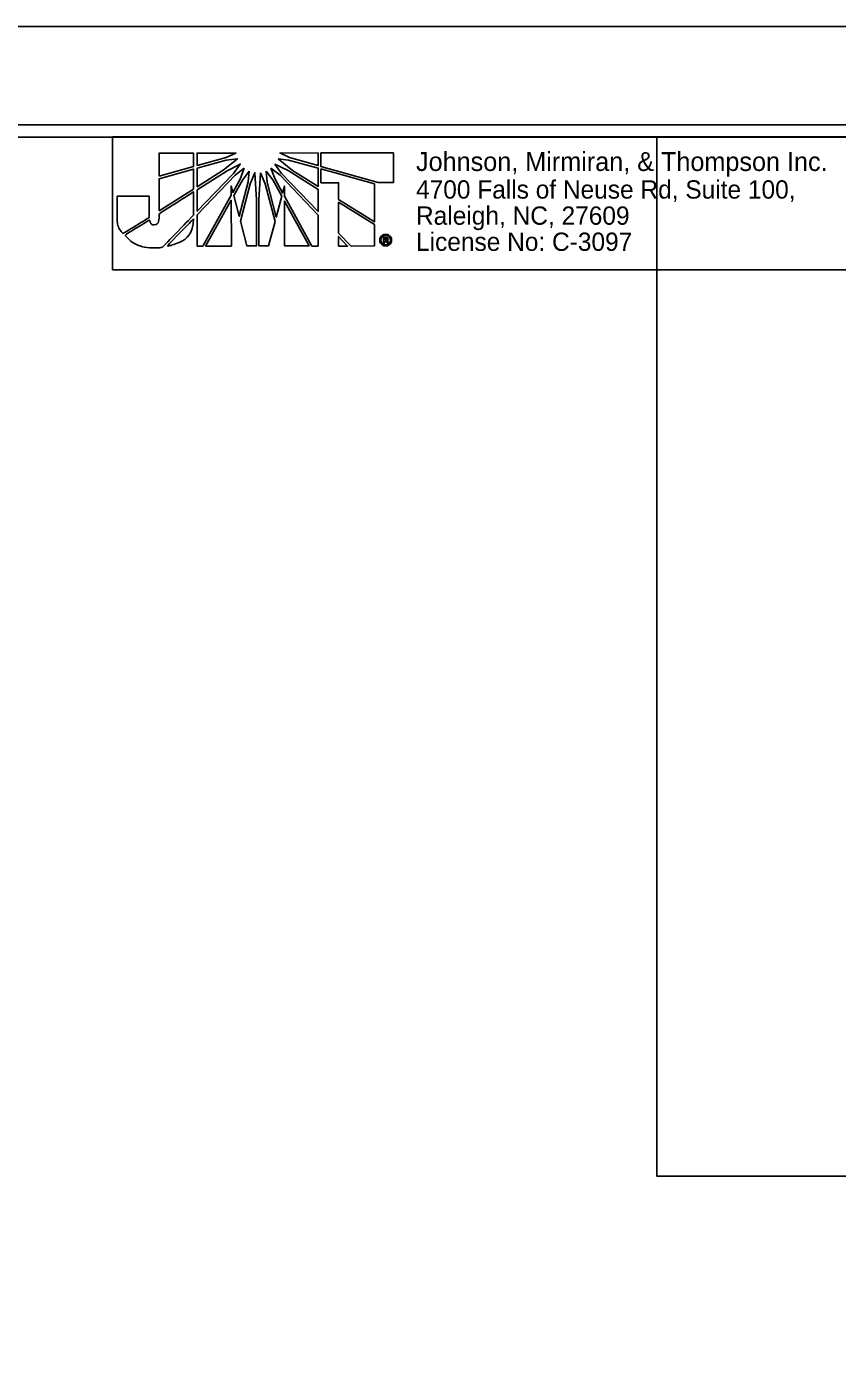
# Model space of a CAD drawing. Extents: x 1640342 to 1730599, y 538663 to 843747.
# Drawn here: x 1730100.5 to 1730133.5, y 539076.9 to 539130.9 of the extents above; entities that cross this region are included whole.
import ezdxf

# ---------------------------------------------------------------- set-up
doc = ezdxf.new("R2010")
doc.units = 0
for name, color, linetype in [('Prop Dimension Text', 7, 'Continuous'), ('Sheet Clip Boundary CELL', 7, 'Continuous'), ('Sheet Layout Plan Border', 7, 'Continuous'), ('Sheet Plan CELL', 7, 'Continuous'), ('Sheet Plan Layout CELL', 7, 'Continuous'), ('Sheet Plot Border Inside CELL', 7, 'Continuous'), ('Sheet Plot Border Outside CELL', 7, 'Continuous')]:
    doc.layers.add(name, color=color, linetype=linetype)

msp = doc.modelspace()

# ---------------------------------------------------------------- linework, layer by layer
at = {"layer": 'Prop Dimension Text'}
for p, q in [((1730107.302, 539125.758), (1730105.899, 539125.756)), ((1730105.899, 539125.756), (1730105.9, 539124.826)), ((1730107.302, 539125.216), (1730107.302, 539125.758)), ((1730109.027, 539125.766), (1730107.448, 539125.765)), ((1730107.448, 539125.765), (1730107.448, 539125.262)), ((1730108.624, 539125.588), (1730109.027, 539125.766)), ((1730112.37, 539125.763), (1730110.814, 539125.768)), ((1730110.814, 539125.768), (1730111.208, 539125.583)), ((1730112.37, 539125.258), (1730112.37, 539125.763)), ((1730115.428, 539125.772), (1730112.479, 539125.77)), ((1730112.479, 539125.77), (1730112.479, 539125.228)), ((1730115.43, 539124.564), (1730115.428, 539125.772)), ((1730105.9, 539124.826), (1730107.302, 539125.216)), ((1730107.448, 539125.262), (1730108.624, 539125.588)), ((1730108.624, 539125.479), (1730107.448, 539125.154)), ((1730107.448, 539125.154), (1730107.449, 539124.394)), ((1730108.502, 539125.062), (1730109.082, 539125.535)), ((1730109.082, 539125.535), (1730108.624, 539125.479)), ((1730109.198, 539125.317), (1730108.664, 539125.046)), ((1730108.928, 539124.937), (1730109.198, 539125.317)), ((1730109.361, 539125.148), (1730108.988, 539124.861)), ((1730109.19, 539124.699), (1730109.361, 539125.148)), ((1730110.449, 539125.15), (1730110.621, 539124.701)), ((1730110.822, 539124.863), (1730110.449, 539125.15)), ((1730110.613, 539125.319), (1730110.884, 539124.932)), ((1730111.155, 539125.048), (1730110.613, 539125.319)), ((1730110.736, 539125.536), (1730111.324, 539125.055)), ((1730111.169, 539125.481), (1730110.736, 539125.536)), ((1730112.37, 539125.151), (1730111.169, 539125.481)), ((1730111.208, 539125.583), (1730112.37, 539125.258)), ((1730112.362, 539124.408), (1730112.37, 539125.151)), ((1730112.479, 539125.228), (1730112.479, 539125.212)), ((1730112.479, 539125.212), (1730114.802, 539124.563)), ((1730107.302, 539125.114), (1730105.9, 539124.719)), ((1730105.9, 539124.719), (1730105.901, 539123.411)), ((1730107.303, 539124.301), (1730107.302, 539125.114)), ((1730107.449, 539124.394), (1730108.502, 539125.062)), ((1730108.664, 539125.046), (1730107.449, 539124.271)), ((1730107.45, 539123.396), (1730108.928, 539124.937)), ((1730108.988, 539124.861), (1730107.45, 539123.248)), ((1730108.896, 539124.164), (1730109.19, 539124.699)), ((1730109.285, 539124.667), (1730108.936, 539124.032)), ((1730109.562, 539125.024), (1730109.285, 539124.667)), ((1730109.523, 539124.591), (1730109.562, 539125.024)), ((1730109.794, 539124.961), (1730109.602, 539124.512)), ((1730109.855, 539123.855), (1730109.794, 539124.961)), ((1730110.025, 539124.962), (1730109.954, 539123.855)), ((1730110.211, 539124.513), (1730110.025, 539124.962)), ((1730110.25, 539125.024), (1730110.296, 539124.575)), ((1730110.521, 539124.668), (1730110.25, 539125.024)), ((1730110.885, 539124.011), (1730110.521, 539124.668)), ((1730110.621, 539124.701), (1730110.922, 539124.143)), ((1730112.363, 539123.239), (1730110.822, 539124.863)), ((1730110.884, 539124.932), (1730112.363, 539123.385)), ((1730112.362, 539124.283), (1730111.155, 539125.048)), ((1730111.324, 539125.055), (1730112.362, 539124.408)), ((1730112.479, 539125.128), (1730112.479, 539125.119)), ((1730114.654, 539124.51), (1730112.479, 539125.128)), ((1730112.479, 539125.119), (1730112.48, 539124.554)), ((1730105.901, 539123.411), (1730107.303, 539124.301)), ((1730107.449, 539124.271), (1730107.45, 539123.396)), ((1730108.827, 539124.048), (1730108.826, 539124.419)), ((1730108.826, 539124.419), (1730108.896, 539124.164)), ((1730109.161, 539123.19), (1730109.523, 539124.591)), ((1730109.602, 539124.512), (1730109.208, 539122.995)), ((1730110.615, 539122.973), (1730110.211, 539124.513)), ((1730110.296, 539124.575), (1730110.661, 539123.159)), ((1730110.922, 539124.143), (1730110.994, 539124.421)), ((1730110.994, 539124.421), (1730110.994, 539124.011)), ((1730112.363, 539123.385), (1730112.362, 539124.283)), ((1730112.48, 539124.554), (1730113.2, 539124.555)), ((1730113.2, 539124.555), (1730113.201, 539123.881)), ((1730114.655, 539122.961), (1730114.654, 539124.51)), ((1730114.802, 539124.563), (1730115.43, 539124.564)), ((1730107.683, 539121.975), (1730108.827, 539124.048)), ((1730108.827, 539123.847), (1730107.792, 539121.975)), ((1730108.838, 539121.976), (1730108.827, 539123.847)), ((1730108.936, 539124.032), (1730109.161, 539123.19)), ((1730109.857, 539121.984), (1730109.855, 539123.855)), ((1730109.954, 539123.855), (1730109.956, 539121.984)), ((1730110.661, 539123.159), (1730110.885, 539124.011)), ((1730110.994, 539124.011), (1730112.116, 539121.979)), ((1730112.001, 539121.986), (1730110.994, 539123.809)), ((1730110.994, 539123.809), (1730110.996, 539121.985)), ((1730113.201, 539123.881), (1730114.655, 539122.961)), ((1730113.201, 539123.765), (1730113.202, 539122.51)), ((1730114.655, 539122.852), (1730113.201, 539123.765)), ((1730107.45, 539123.248), (1730107.451, 539121.975)), ((1730109.208, 539122.995), (1730109.472, 539121.984)), ((1730112.364, 539121.979), (1730112.363, 539123.239)), ((1730110.345, 539121.984), (1730110.615, 539122.973)), ((1730113.202, 539122.51), (1730113.705, 539121.981)), ((1730114.656, 539121.982), (1730114.655, 539122.852)), ((1730115.113, 539122.456), (1730115.113, 539122.411)), ((1730115.113, 539122.411), (1730115.113, 539122.456)), ((1730107.451, 539121.975), (1730107.683, 539121.975)), ((1730107.792, 539121.975), (1730108.838, 539121.976)), ((1730109.472, 539121.984), (1730109.857, 539121.984)), ((1730109.956, 539121.984), (1730110.345, 539121.984)), ((1730110.996, 539121.985), (1730112.001, 539121.986)), ((1730112.116, 539121.979), (1730112.364, 539121.979)), ((1730113.566, 539121.981), (1730113.202, 539122.374)), ((1730113.202, 539122.374), (1730113.202, 539121.98)), ((1730113.202, 539121.98), (1730113.566, 539121.981)), ((1730113.705, 539121.981), (1730114.656, 539121.982)), ((1730115.026, 539122.114), (1730115.025, 539122.329)), ((1730115.025, 539122.329), (1730115.113, 539122.329)), ((1730115.074, 539122.114), (1730115.026, 539122.114)), ((1730115.113, 539122.288), (1730115.074, 539122.288)), ((1730115.074, 539122.288), (1730115.074, 539122.237)), ((1730115.074, 539122.237), (1730115.113, 539122.237)), ((1730115.113, 539122.198), (1730115.074, 539122.198)), ((1730115.074, 539122.198), (1730115.074, 539122.114)), ((1730115.113, 539122.329), (1730115.113, 539122.288)), ((1730115.113, 539122.288), (1730115.113, 539122.329)), ((1730115.113, 539122.329), (1730115.127, 539122.329)), ((1730115.119, 539122.288), (1730115.113, 539122.288)), ((1730115.113, 539122.237), (1730115.113, 539122.198)), ((1730115.113, 539122.198), (1730115.113, 539122.237)), ((1730115.113, 539122.237), (1730115.115, 539122.237)), ((1730115.115, 539122.198), (1730115.113, 539122.198)), ((1730115.113, 539122.031), (1730115.114, 539121.984)), ((1730115.114, 539121.984), (1730115.113, 539122.031)), ((1730115.113, 539122.031), (1730115.115, 539122.031)), ((1730115.115, 539121.984), (1730115.114, 539121.984))]:
    msp.add_line(p, q, dxfattribs=at)
msp.add_lwpolyline([(1730104.001, 539121.01), (1730133.983, 539121.01), (1730133.983, 539126.42), (1730104.001, 539126.42)], close=True, dxfattribs=at)
for points in [[(1730105.9, 539124.826), (1730107.302, 539125.216), (1730107.302, 539125.758), (1730105.899, 539125.756), (1730105.9, 539124.826)], [(1730108.624, 539125.588), (1730109.027, 539125.766), (1730107.448, 539125.765), (1730107.448, 539125.262), (1730108.624, 539125.588)], [(1730111.208, 539125.583), (1730112.37, 539125.258), (1730112.37, 539125.763), (1730110.814, 539125.768), (1730111.208, 539125.583)], [(1730115.428, 539125.772), (1730112.479, 539125.77), (1730112.479, 539125.228), (1730112.479, 539125.212), (1730114.802, 539124.563), (1730115.43, 539124.564), (1730115.428, 539125.772)], [(1730107.448, 539125.154), (1730107.449, 539124.394), (1730108.502, 539125.062), (1730109.082, 539125.535), (1730108.624, 539125.479), (1730107.448, 539125.154)], [(1730107.449, 539124.271), (1730107.45, 539123.396), (1730108.928, 539124.937), (1730109.198, 539125.317), (1730108.664, 539125.046), (1730107.449, 539124.271)], [(1730109.361, 539125.148), (1730108.988, 539124.861), (1730107.45, 539123.248), (1730107.451, 539121.975), (1730107.683, 539121.975), (1730108.827, 539124.048), (1730108.826, 539124.419), (1730108.896, 539124.164), (1730109.19, 539124.699), (1730109.361, 539125.148)], [(1730110.449, 539125.15), (1730110.621, 539124.701), (1730110.922, 539124.143), (1730110.994, 539124.421), (1730110.994, 539124.011), (1730112.116, 539121.979), (1730112.364, 539121.979), (1730112.363, 539123.239), (1730110.822, 539124.863), (1730110.449, 539125.15)], [(1730110.613, 539125.319), (1730110.884, 539124.932), (1730112.363, 539123.385), (1730112.362, 539124.283), (1730111.155, 539125.048), (1730110.613, 539125.319)], [(1730110.736, 539125.536), (1730111.324, 539125.055), (1730112.362, 539124.408), (1730112.37, 539125.151), (1730111.169, 539125.481), (1730110.736, 539125.536)], [(1730105.901, 539123.411), (1730107.303, 539124.301), (1730107.302, 539125.114), (1730105.9, 539124.719), (1730105.901, 539123.411)], [(1730109.562, 539125.024), (1730109.285, 539124.667), (1730108.936, 539124.032), (1730109.161, 539123.19), (1730109.523, 539124.591), (1730109.562, 539125.024)], [(1730109.602, 539124.512), (1730109.208, 539122.995), (1730109.472, 539121.984), (1730109.857, 539121.984), (1730109.855, 539123.855), (1730109.794, 539124.961), (1730109.602, 539124.512)], [(1730110.025, 539124.962), (1730109.954, 539123.855), (1730109.956, 539121.984), (1730110.345, 539121.984), (1730110.615, 539122.973), (1730110.211, 539124.513), (1730110.025, 539124.962)], [(1730110.25, 539125.024), (1730110.296, 539124.575), (1730110.661, 539123.159), (1730110.885, 539124.011), (1730110.521, 539124.668), (1730110.25, 539125.024)], [(1730112.479, 539125.128), (1730112.479, 539125.119), (1730112.48, 539124.554), (1730113.2, 539124.555), (1730113.201, 539123.881), (1730114.655, 539122.961), (1730114.654, 539124.51), (1730112.479, 539125.128)], [(1730107.792, 539121.975), (1730108.838, 539121.976), (1730108.827, 539123.847), (1730107.792, 539121.975)], [(1730110.996, 539121.985), (1730112.001, 539121.986), (1730110.994, 539123.809), (1730110.996, 539121.985)], [(1730113.201, 539123.765), (1730113.202, 539122.51), (1730113.705, 539121.981), (1730114.656, 539121.982), (1730114.655, 539122.852), (1730113.201, 539123.765), (1730113.201, 539123.765)], [(1730113.202, 539121.98), (1730113.202, 539121.98), (1730113.566, 539121.981), (1730113.202, 539122.374), (1730113.202, 539121.98)], [(1730115.207, 539122.165), (1730115.207, 539122.154), (1730115.209, 539122.146), (1730115.209, 539122.138), (1730115.215, 539122.115), (1730115.17, 539122.115)]]:
    msp.add_lwpolyline(points, dxfattribs=at)
for points, degree in [([(1730105.7, 539122.844), (1730105.617, 539122.844), (1730105.545, 539122.89), (1730105.515, 539123.045), (1730105.515, 539123.045), (1730104.508, 539122.421), (1730104.508, 539122.421), (1730104.819, 539122.095), (1730105.314, 539121.901), (1730105.733, 539121.901), (1730105.842, 539121.901), (1730105.925, 539121.911), (1730106.041, 539121.934), (1730106.041, 539121.934), (1730107.304, 539123.241), (1730107.304, 539123.241), (1730107.304, 539123.241), (1730107.303, 539124.186), (1730107.303, 539124.186), (1730107.303, 539124.186), (1730105.901, 539123.293), (1730105.901, 539123.293), (1730105.901, 539122.939), (1730105.816, 539122.844), (1730105.7, 539122.844)], 3), ([(1730105.7, 539122.844), (1730105.617, 539122.844), (1730105.545, 539122.89), (1730105.515, 539123.045), (1730105.515, 539123.045), (1730104.508, 539122.421), (1730104.508, 539122.421), (1730104.819, 539122.095), (1730105.314, 539121.901), (1730105.733, 539121.901), (1730105.842, 539121.901), (1730105.925, 539121.911), (1730106.041, 539121.934), (1730106.041, 539121.934), (1730107.304, 539123.241), (1730107.304, 539123.241), (1730107.304, 539123.241), (1730107.303, 539124.186), (1730107.303, 539124.186), (1730107.303, 539124.186), (1730105.901, 539123.293), (1730105.901, 539123.293), (1730105.901, 539122.939), (1730105.816, 539122.844), (1730105.7, 539122.844)], 3), ([(1730105.497, 539124.013), (1730105.497, 539124.013), (1730104.199, 539124.011), (1730104.199, 539124.011), (1730104.199, 539124.011), (1730104.199, 539123.199), (1730104.199, 539123.199), (1730104.199, 539123.199), (1730104.199, 539123.113), (1730104.199, 539123.113), (1730104.2, 539122.858), (1730104.283, 539122.657), (1730104.432, 539122.488), (1730104.432, 539122.488), (1730105.498, 539123.137), (1730105.498, 539123.154), (1730105.498, 539123.154), (1730105.497, 539124.013), (1730105.497, 539124.013)], 3), ([(1730107.304, 539123.093), (1730107.304, 539123.093), (1730106.212, 539121.964), (1730106.212, 539121.964), (1730106.747, 539122.097), (1730107.279, 539122.452), (1730107.304, 539123.093)], 3), ([(1730115.114, 539121.984), (1730115.049, 539121.984), (1730114.993, 539122.007), (1730114.946, 539122.054), (1730114.899, 539122.099), (1730114.875, 539122.155), (1730114.875, 539122.221), (1730114.875, 539122.288), (1730114.899, 539122.344), (1730114.945, 539122.387), (1730114.992, 539122.432), (1730115.047, 539122.456), (1730115.113, 539122.456)], 3), ([(1730115.113, 539122.456), (1730115.179, 539122.456), (1730115.236, 539122.432), (1730115.283, 539122.388), (1730115.33, 539122.345), (1730115.353, 539122.288), (1730115.353, 539122.222)], 3), ([(1730115.113, 539122.411), (1730115.06, 539122.411), (1730115.016, 539122.393), (1730114.979, 539122.358), (1730114.942, 539122.321), (1730114.922, 539122.274), (1730114.922, 539122.222), (1730114.922, 539122.169), (1730114.942, 539122.122), (1730114.979, 539122.085), (1730115.016, 539122.048), (1730115.061, 539122.031), (1730115.113, 539122.031)], 3), ([(1730115.115, 539122.031), (1730115.168, 539122.031), (1730115.213, 539122.048), (1730115.25, 539122.085), (1730115.287, 539122.122), (1730115.306, 539122.169), (1730115.306, 539122.222), (1730115.306, 539122.275), (1730115.287, 539122.321), (1730115.25, 539122.358), (1730115.213, 539122.393), (1730115.168, 539122.411), (1730115.113, 539122.411)], 3), ([(1730115.115, 539122.237), (1730115.146, 539122.237), (1730115.162, 539122.247), (1730115.162, 539122.265), (1730115.162, 539122.28), (1730115.148, 539122.288), (1730115.119, 539122.288)], 3), ([(1730115.353, 539122.222), (1730115.353, 539122.156), (1730115.33, 539122.099), (1730115.285, 539122.052), (1730115.238, 539122.007), (1730115.182, 539121.984), (1730115.115, 539121.984)], 3), ([(1730115.152, 539122.191), (1730115.146, 539122.194), (1730115.135, 539122.198), (1730115.115, 539122.198)], 2), ([(1730115.127, 539122.329), (1730115.181, 539122.329), (1730115.209, 539122.308), (1730115.209, 539122.265), (1730115.209, 539122.245), (1730115.201, 539122.23), (1730115.184, 539122.218)], 3), ([(1730115.17, 539122.115), (1730115.164, 539122.126), (1730115.16, 539122.138), (1730115.16, 539122.153), (1730115.16, 539122.173), (1730115.158, 539122.185), (1730115.152, 539122.191)], 3), ([(1730115.184, 539122.218), (1730115.197, 539122.21), (1730115.205, 539122.193), (1730115.207, 539122.165)], 2)]:
    msp.add_open_spline(points, degree=degree, dxfattribs=at)
at = {"layer": 'Sheet Clip Boundary CELL'}
msp.add_lwpolyline([(1729883.99, 538916.418), (1730163.993, 538916.418), (1730163.993, 539084.12), (1730126.14, 539084.12), (1730126.14, 539126.418), (1729883.99, 539126.418)], close=True, dxfattribs=at)
at = {"layer": 'Sheet Layout Plan Border'}
msp.add_lwpolyline([(1729883.99, 538916.418), (1730163.993, 538916.418), (1730163.993, 539084.12), (1730126.14, 539084.12), (1730126.14, 539126.418), (1729883.99, 539126.418)], close=True, dxfattribs=at)
at = {"layer": 'Sheet Plan CELL'}
for points in [[(1729873.99, 538916.418), (1729873.985, 539126.413), (1730133.983, 539126.42), (1730133.985, 539096.408), (1730173.993, 539096.405), (1730173.993, 538916.418)], [(1730173.998, 539126.418), (1729873.99, 539126.418), (1729873.99, 538916.418), (1730173.993, 538916.418)]]:
    msp.add_lwpolyline(points, close=True, dxfattribs=at)
at = {"layer": 'Sheet Plan Layout CELL'}
for points in [[(1729873.985, 539126.413), (1729873.99, 538916.418), (1730173.99, 538916.418), (1730173.99, 539084.12), (1730126.14, 539084.12), (1730126.14, 539126.418)], [(1730126.14, 539084.12), (1730173.995, 539084.12), (1730174, 539126.418), (1730126.14, 539126.418)]]:
    msp.add_lwpolyline(points, close=True, dxfattribs=at)
at = {"layer": 'Sheet Plot Border Inside CELL'}
msp.add_lwpolyline([(1729843.293, 538915.915), (1730176.49, 538915.918), (1730176.493, 539126.915), (1729843.293, 539126.915)], close=True, dxfattribs=at)
at = {"layer": 'Sheet Plot Border Outside CELL'}
msp.add_lwpolyline([(1729840.693, 538911.915), (1730177.393, 538911.915), (1730177.393, 539130.915), (1729840.693, 539130.915)], close=True, dxfattribs=at)

# ---------------------------------------------------------------- texts
at = {"layer": 'Prop Dimension Text'}
for s, height, p in [('Johnson, Mirmiran, & Thompson Inc.', 0.76607, (1730116.348, 539125.035)), ('4700 Falls of Neuse Rd, Suite 100, ', 0.74418, (1730116.348, 539123.911)), ('Raleigh, NC, 27609', 0.74418, (1730116.348, 539122.847)), ('License No: C-3097', 0.74418, (1730116.348, 539121.784))]:
    msp.add_text(s, height=height, rotation=360, dxfattribs=at).set_placement(p)

doc.saveas('drawing.dxf')
